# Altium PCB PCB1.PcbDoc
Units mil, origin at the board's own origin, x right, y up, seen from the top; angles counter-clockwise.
Board outline 3360 x 2065 mil, 2 copper layers (Top Layer, Bottom Layer); 16 components, 42 nets, 96 pads, 3 vias.
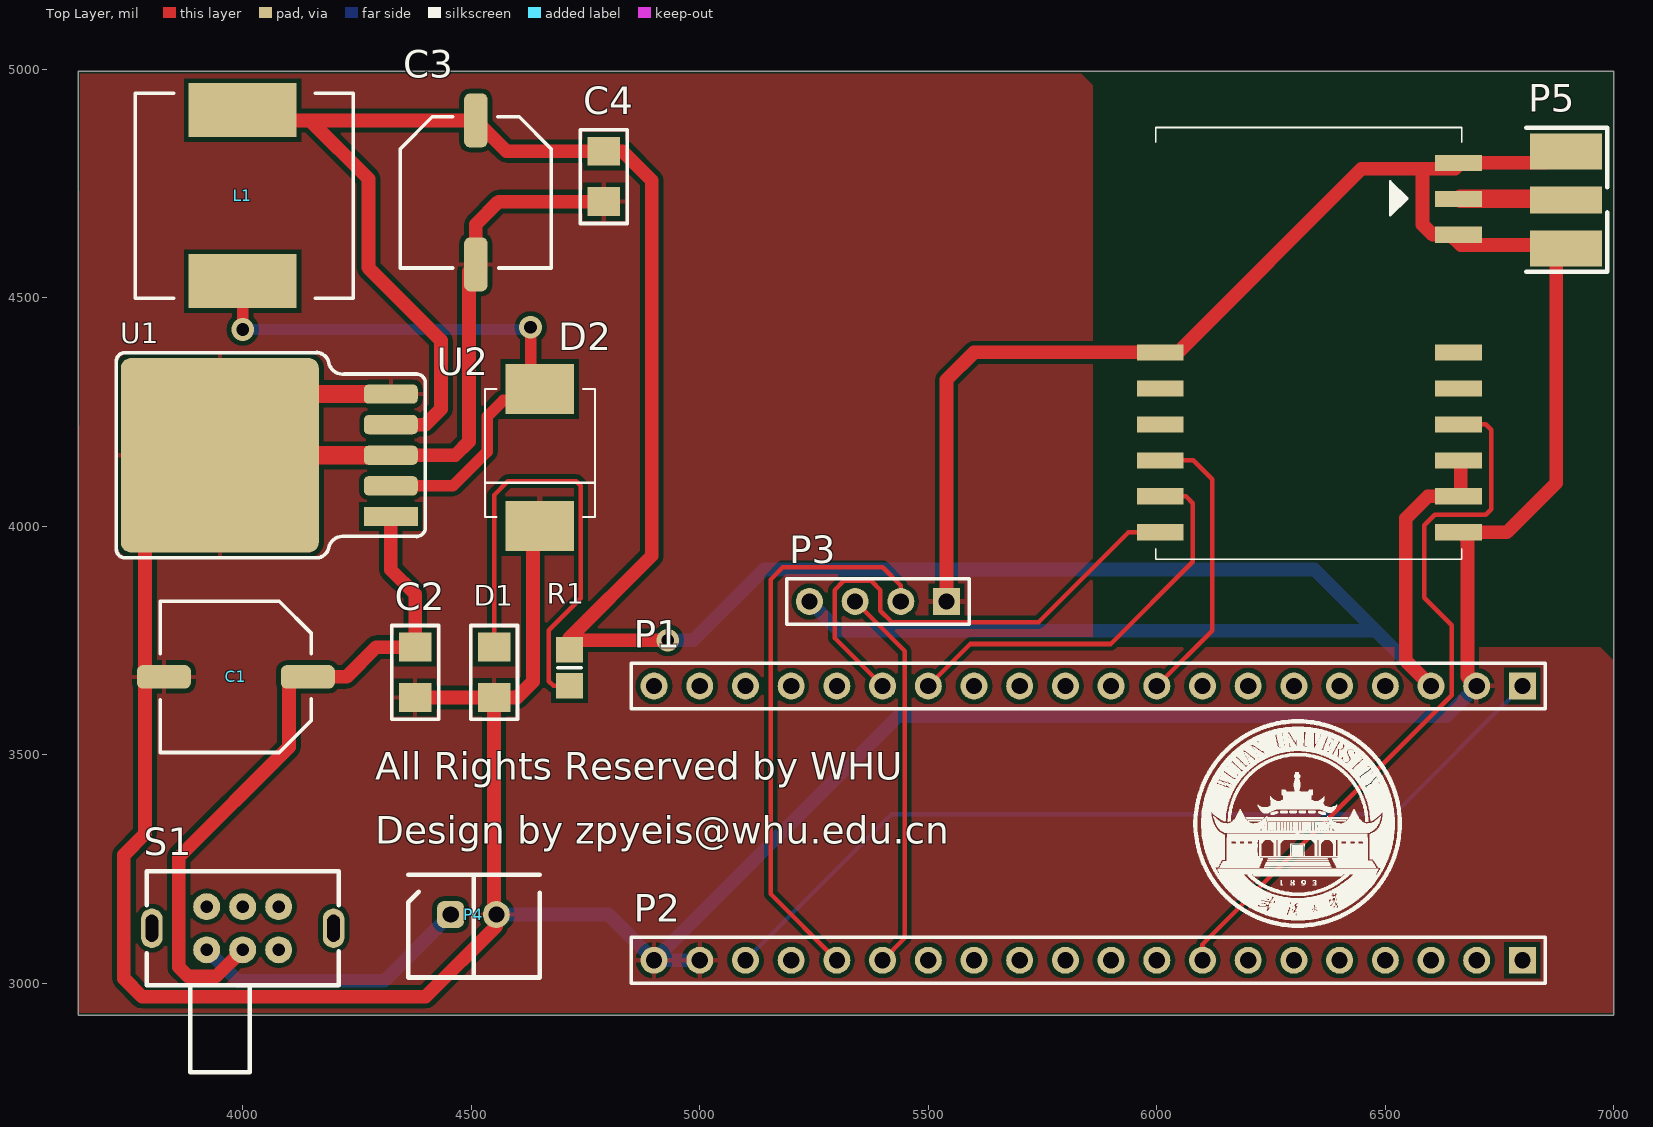
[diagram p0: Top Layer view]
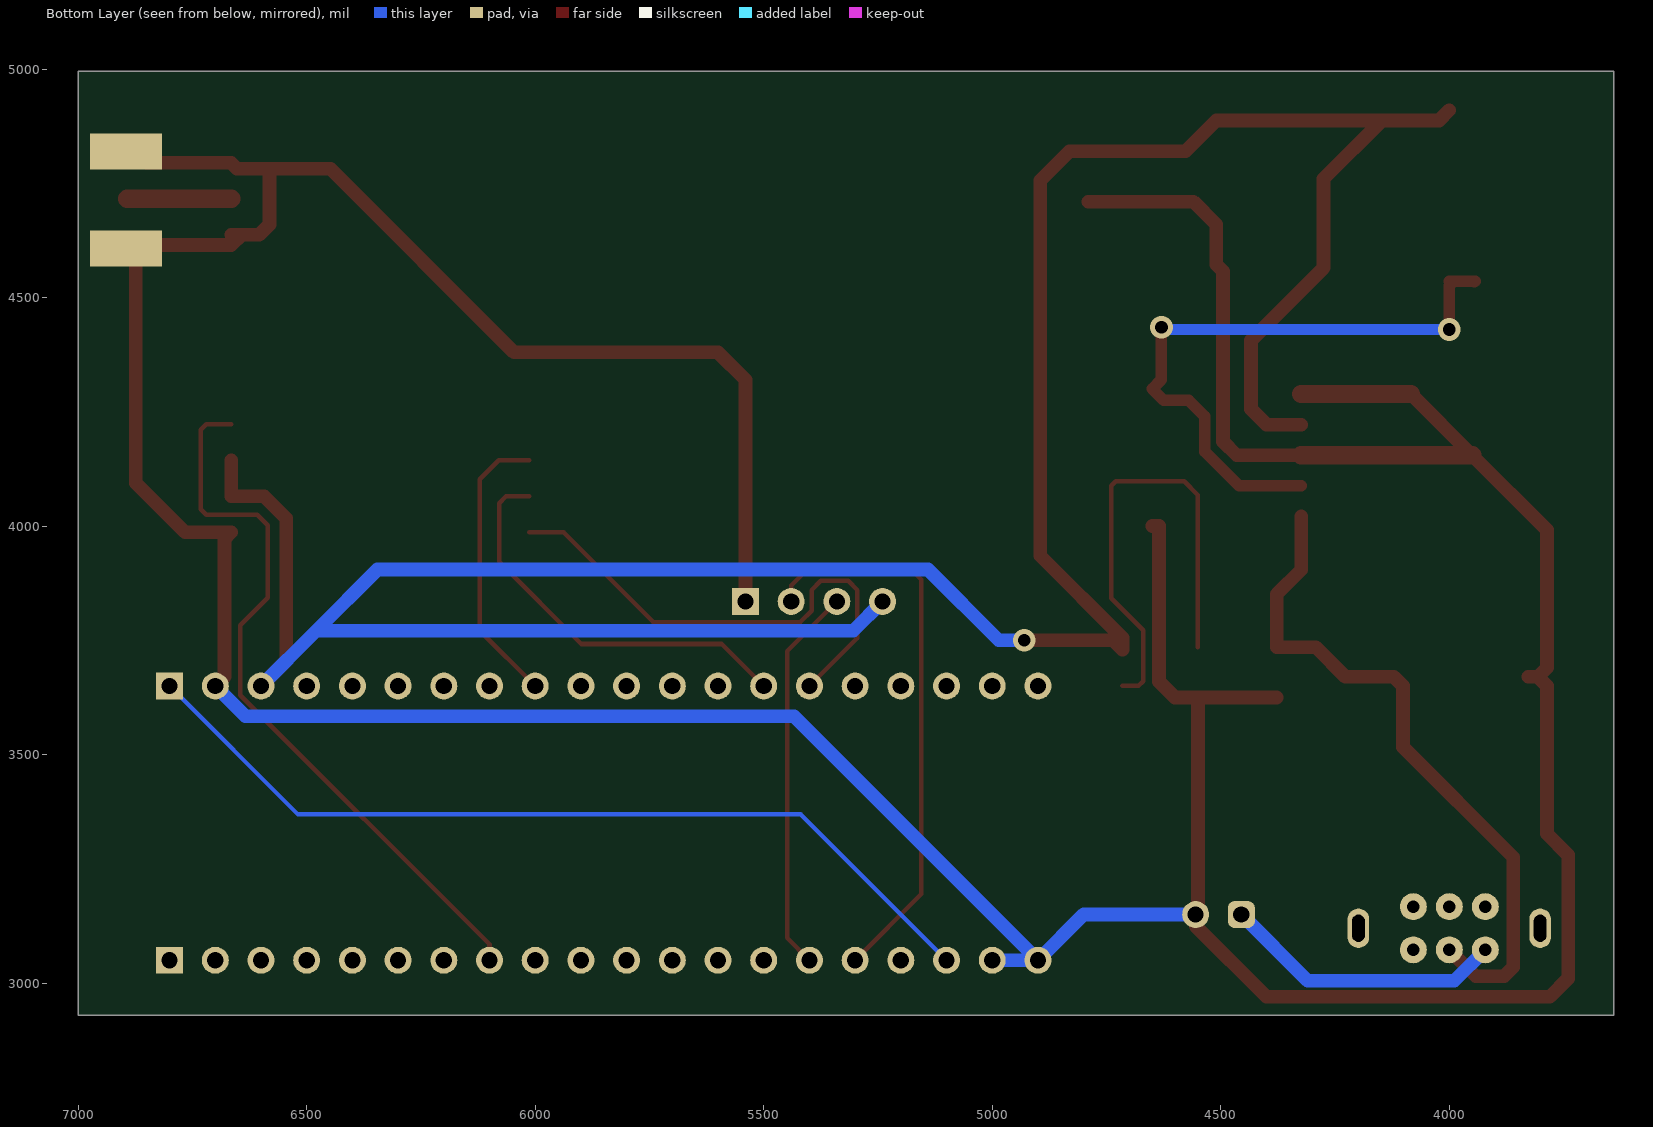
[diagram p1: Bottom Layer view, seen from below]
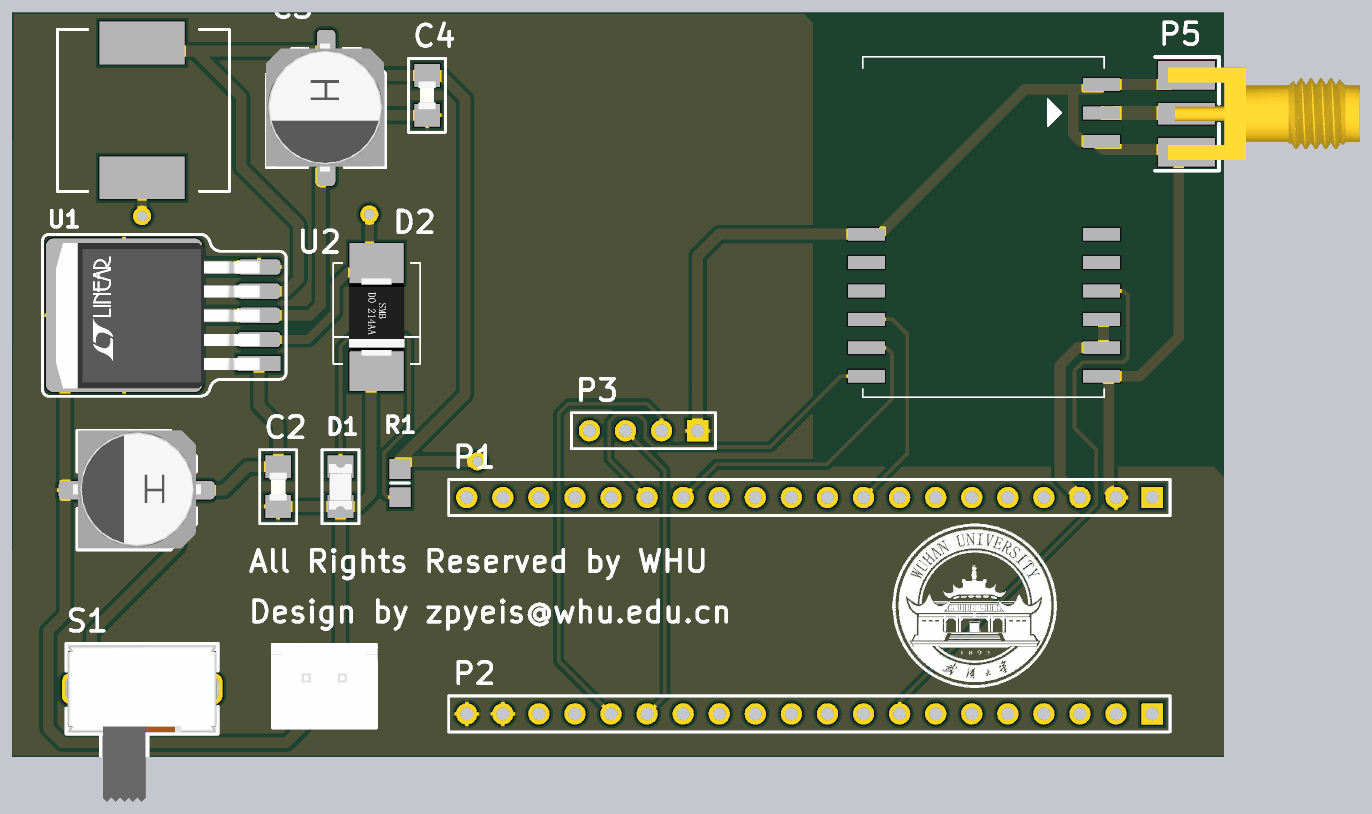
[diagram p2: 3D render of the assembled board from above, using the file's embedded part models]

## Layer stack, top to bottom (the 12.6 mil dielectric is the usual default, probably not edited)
Top Solder: solder mask 0.4, Solder Resist, Dk 3.5
Top Layer: signal copper 1.4
Dielectric 1: dielectric 12.6, FR-4, Dk 4.8
Bottom Layer: signal copper 1.4
Bottom Solder: solder mask 0.4, Solder Resist, Dk 3.5

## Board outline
3640,2930 3640,4995 7000,4995 7000,2930

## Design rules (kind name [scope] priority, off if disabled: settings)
Clearance [All] p1: gap=10 ignorepadtopadclearanceinfootprint=FALSE except(0: Arc-Hole Track-Hole SMDPad-Hole THPad-Hole Via-Hole Fill-Hole Poly-Hole Region-Hole Text-Hole; 2: Arc-Text Track-Text SMDPad-Text THPad-Text Via-Text Fill-Text Poly-Text Region-Text Text-Text)
PolygonConnect [All] p1: connectstyle=Relief reliefconductorwidth=10 reliefentries=4 polygonreliefangle="90 Angle" airgapwidth=10
RoutingVias [All] p1: holewidth=28 width=50 viastyle="Through Hole" minholewidth=28 minwidth=50 maxholewidth=28 maxwidth=50
SilkToSolderMaskClearance [IsPad] p1: minsilkscreentomaskgap=1 clearancetoexposedcopper=TRUE
SolderMaskExpansion [All] p1: expansion=4
Width [All] p1: maxlimit=40 minlimit=10 preferedwidth=10 minimp=50.000000 maximp=50.000000 favimp=50.000000
29 further rules are at their usual default settings.

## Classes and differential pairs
component class Sheet1: C1 C2 C3 C4 D1 L1 P1 P3 P4 P5 R1 S1 U1 U2

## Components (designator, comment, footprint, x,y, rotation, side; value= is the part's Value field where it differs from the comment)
C1 "CAP1" CAP+ 3985,3670 r180 top
C2 "CAP" CAP 4377.36,3680 r270 top
C3 "CAP1" CAP+ 4510,4730 r270 top
C4 "CAP" CAP 4790,4765 r270 top
D1 "LED" LED 4550,3680.12 r270 top
D2 "SS34" SS34 4650,4150 r90 top
L1 "Inductor" 470 4000,4910 r270 top value=47uH
P1 "STM32" HDR1X20 6800,3650 r180 top
P2 "STM32" HDR1X20 6800,3050 r180 top
P3 "Sensor" HDR1X4 5540,3835 r180 top
P4 "Header 2" HDR2 4455,3150 r0 top
P5 "SMB" SMA-KE 6895,4713.7 r270 top
R1 "4.7k" 6-0805_M 4715,3690 r270 top
S1 "SW-SPST" SK-22D02 4000,3120 r0 top
U1 "LM2596-5V" LM2596S 4137.01,4155 r90 top
U2 "LORA" LORA 4413.84,3842.18 r90 top

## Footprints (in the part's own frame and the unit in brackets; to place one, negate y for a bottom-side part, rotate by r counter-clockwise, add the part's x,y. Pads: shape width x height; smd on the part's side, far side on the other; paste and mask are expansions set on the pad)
6-0805_M [mm] "Chip Resistor, Body 2.0x1.2mm, IPC Low Density"
  rect 1.4x1.5 smd: 1(-1,0) 2(1,0)
  silkscreen extent 0,-0.65 0,0.65, body extent -1.07,-0.7 1.07,0.7, height 0.7
470 [mm]
  rect 3x6 smd: 1(0,0) 2(9.5,0)
  silkscreen extent -0.95,-5.97 10.45,6.15
CAP [mm]
  rect 1.6x1.8 smd: 1(-1.4,0) 2(1.4,0)
  silkscreen extent -2.6,-1.3 2.62,1.3, body extent -1,-0.62 1,0.63, height 0.5
CAP+ [mm]
  rrect50% 3x1.3 smd: 1(-4,0) 2(4,0)
  silkscreen extent -4.2,-4.2 4.2,4.2, body extent -4.52,-4.22 4.48,4.08, height 10.5
HDR1X4 [mm] "Connector; Header; 4 Position"
  rect 1.5x1.5 hole 0.9: 1(0,0)
  round 1.5 hole 0.9: 2(2.54,0) 3(5.08,0) 4(7.62,0)
  silkscreen extent -1.27,-1.27 8.89,1.27
HDR1X20 [mm] "Connector; Header; 20 Position"
  rect 1.5x1.5 hole 0.9: 1(0,0)
  round 1.5 hole 0.9: 2(2.54,0) 3(5.08,0) 4(7.62,0) 5(10.16,0) 6(12.7,0) 7(15.24,0) 8(17.78,0) 9(20.32,0) 10(22.86,0) 11(25.4,0) 12(27.94,0) 13(30.48,0) 14(33.02,0) 15(35.56,0) 16(38.1,0) 17(40.64,0) 18(43.18,0) 19(45.72,0) 20(48.26,0)
  silkscreen extent -1.27,-1.27 49.53,1.27
HDR2 [mm]
  rrect50% 1.5x1.5 hole 0.9: 1(0,0)
  round 1.5 hole 0.9: 2(2.54,0)
  silkscreen extent -2.36,-3.5 4.94,2.2, body extent -2.48,-3.55 5.02,2.45, height 7
LED [mm]
  rect 1.6x1.8 smd: 1(-1.4,0) 2(1.4,0)
  silkscreen extent -2.6,-1.3 2.62,1.3, body extent -1.57,-0.8 1.63,0.8, height 1.1
LM2596S [mm]
  rrect10% 10.8x11 smd: 0(0,4.75)
  rect 1.07x3 smd: 1(-3.4,-4.75)
  rrect50% 1.07x3 smd: 2(-1.7,-4.75) 3(0,-4.75) 4(1.7,-4.75) 5(3.4,-4.75)
  silkscreen extent -5.7,-6.66 5.7,10.5, body extent -5.14,-4.8 5.09,9.55, height 4.48
LORA [mm]
  rect 0.9x2.6 smd: 1(24.193,-57.052) 2(22.193,-57.052) 3(20.193,-57.052) 4(13.661,-57.052) 5(11.661,-57.052) 6(9.661,-57.052) 7(7.661,-57.052) 8(5.661,-57.052) 9(3.661,-57.052) 10(3.661,-40.484) 11(5.661,-40.484) 12(7.661,-40.484) 13(9.661,-40.484) 14(11.661,-40.484) 15(13.661,-40.484)
  silkscreen extent 2.16,-57.23 26.16,-40.23
SK-22D02 [mm] "10.4x6.1x4.2mm(长宽高)，脚距：2mm"
  oval 1.2x2.2 hole 0.7 slot 1.5 at 90 deg: 0(-5.05,0) 0(5.05,0)
  round 1.5 hole 0.7: 1(-2,-1.2) 2(0,-1.2) 3(2,-1.2) 4(2,1.2) 5(0,1.2) 6(-2,1.2)
  silkscreen extent -5.33,-8 5.33,3.17, body extent -5.27,-7.96 5.25,3.05, height 5.59
SMA-KE [mm] "SMA 偏脚射频天线座"
  rect 1.5x4 smd: 1(0,0)
  rect 2x4 smd: 2(-2.7,0) 2(2.7,0)
  rect 2x4 smd far side: 3(-2.7,0) 3(2.7,0)
  silkscreen extent -4,-2.2 4,2.3, body extent -3.25,-1.3 3.25,12.2, height 3.75
SS34 [mil]
  rect 110x150 smd: 1(-149.99,0.01) 2(150.01,0.01)
  silkscreen extent -130,-121 150,120, body extent -110,-77 110,77

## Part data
D2: library part DIODE
P1 P2: library part "Header 20", "Header, 20-Pin"
P3: library part "Header 4", "Header, 4-Pin"
P4: "Header, 2-Pin"
P5: "SMB Straight Connector"
R1: library part RES
S1: "Single-Pole, Single-Throw Switch"
U1: library part LM2596S
U2: library part Component_1

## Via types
v1: diameter 50, hole 28, Top Layer to Bottom Layer, 3 vias

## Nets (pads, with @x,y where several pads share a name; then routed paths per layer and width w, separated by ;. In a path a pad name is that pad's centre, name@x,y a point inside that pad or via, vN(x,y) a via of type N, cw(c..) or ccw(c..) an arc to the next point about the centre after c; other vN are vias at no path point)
5V: C3.1 C4.1 L1.1 P1.3 P3.4 R1.1 U1.4 U2.7 U2.8 | length 6871.6
  Top Layer w30: L1.1 4022.52,4887.48 4147.52,4887.48 ; U1.4 4400,4221.93 4434,4255.93 4434,4406 4275,4565 4275,4760 4147.52,4887.48 ; v1(4930,3750) 4735.63,3750 R1.1 4715,3755 4895,3935 4895,4756 4830.88,4820.12 C4.1 4577.36,4820.12 C3.1 4147.52,4887.48 ; P1.3 6545,3705 6545,4017 6593.04,4065.04 6637.32,4065.04 6665,4065.04 6665,4077.52 U2.7@6665,4143.78
  Bottom Layer w30: v1(4930,3750) 4985.63,3750 5140.63,3905 6345,3905 6479,3771 ; P3.4 5304,3771 6479,3771 ; P1.3 6479,3771
GND: C1.2 C2.2 C3.2 C4.2 D1.2 D2.1 P1.2 P2.19 P2.20 P3.1 P4.2 P5.2 U1.0 U1.3 U1.5 U2.1 U2.3 U2.9 U2.15 | length 11211.2
  Top Layer w30: C1.2 C1.2@3806.26,3670 ; U1.0@4083.86,4288.86 U1.0 3786.26,3991.26 3786.26,3690 C1.2@3806.26,3670 ; U1.3 4465,4155 4495,4185 4495,4557.52 C3.2 4510,4659.88 4560,4709.88 C4.2 ; C2.2 4463,3624.88 4463.12,3625 D1.2 ; D2.1 4635,4000.01 4635,3660 4600,3625 D1.2 ; P3.1 5540,4320 5600,4380 5985,4380 6012.68,4380 6046.15,4380 6448.11,4781.96 6587.28,4781.96 ; U2.3@6665,4637.19 U2.3@6642.81,4637.19 ; P1.2 6680,3670 6680,3971.3 6665,3986.3 6680,3986.3 6766,3986.3 6874,4094.3 P5.2@6874,4586.4 ; P5.2@6880,4825 6849.67,4794.67 6665,4794.67 6652.28,4781.96 6637.32,4781.96 6587.28,4781.96 ; P5.2@6895,4607.4 6887.4,4615 6665,4615 U2.3@6642.81,4637.19 ; C1.2@3806.26,3670 3786.26,3650 3786.26,3326.74 3740,3280.48 3740,3010 3780,2970 4400,2970 4555,3125 P4.2 4550,3155 D1.2 ; 6587.28,4781.96 6581.42,4776.09 6581.42,4660 6604.22,4637.19 U2.3@6642.81,4637.19
  Top Layer w40: U1.0 U1.3 ; U1.0@4083.86,4288.86 U1.5
  Bottom Layer w30: P4.2 4800,3150 P2.20 ; P2.19 P2.20 ; P1.2 6634,3584 5434,3584 P2.20
IN+: P4.1 S1.1 | length 621.9
  Bottom Layer w30: S1.1 3989.02,3005 4310,3005 P4.1
NetC1_1: C1.1 C2.1 S1.2 U1.1 | length 1506.6
  Top Layer w30: S1.2 3942.24,3015 3880,3015 3860,3035 3860,3275.48 4101.22,3516.7 4101.22,3650 4121.22,3670 4134,3670 C1.1 4227,3670 4292.12,3735.12 C2.1 4377.36,3851 4324.02,3904.35 U1.1
NetD1_1: D1.1 R1.2 | length 1044.8
  Top Layer w10: D1.1 4550,4068 4580,4098 4730,4098 4740,4088 4740,3842 4670,3772 4670,3660.63 4680,3650.63 R1.2
NetD2_2: D2.2 L1.2 U1.2 | length 1404.2
  Top Layer w25: L1.2@3945,4533.99 3943,4535.99 L1.2 3995,4530.99 4000,4525.99 v1(4000,4430) ; U1.2 4460.07,4088.07 4535,4163 4535,4240 4570,4275 4624.98,4275 D2.2 4630,4320 v1(4630,4435)
  Bottom Layer w25: v1(4000,4430) 4625,4430 v1(4630,4435)
NetP5_1: P5.1 U2.2 | length 230.9
  Top Layer w10: P5.1@6892.77,4715.93 P5.1
  Top Layer w40: U2.2@6665,4715.93 P5.1@6892.77,4715.93
PA0: P2.5
PA1: P2.6
PA2: P2.7
PA3: P2.8 U2.6 | length 1609.2
  Top Layer w10: P2.8 6100,3085 6645,3630 6645,3783 6585,3843 6585,4001.41 6608.59,4025 6720,4025 6732,4037 6732,4210.52 6720,4222.52 U2.6@6665,4222.52
PA4: P2.9
PA5: P2.10
PA6: P2.11
PA7: P2.12
PA8: P1.16
PA9: P1.15 U2.10 | length 1124.4
  Top Layer w10: P1.15 5295,3755 5295,3860 5315,3880 5375,3880 5395,3860 5395,3815 5420,3790 5741.7,3790 5938,3986.3 U2.10@6012.68,3986.3
PA10: P1.14 U2.11 | length 892.2
  Top Layer w10: P1.14 5592,3742 5899,3742 6079,3922 6079,4050 6063.96,4065.04 U2.11@6012.68,4065.04
PA11: P1.13
PA12: P1.12
PA15: P1.11
PB0: P2.13
PB1: P2.14
PB3: P1.10
PB4: P1.9 U2.12 | length 628.2
  Top Layer w10: P1.9 6121,3771 6121,4102.78 6080,4143.78 U2.12@6012.68,4143.78
PB5: P1.8
PB6: P1.7
PB7: P1.6
PB8: P1.5
PB9: P1.4
PB10: P2.15 P3.3 | length 850.4
  Top Layer w10: P3.3 5449,3726 5449,3099 P2.15
PB11: P2.16 P3.2 | length 1240.8
  Top Layer w10: P2.16 5155,3195 5155,3883 5182,3910 5400,3910 5440,3870 P3.2
PB12: P1.20
PB13: P1.19
PB14: P1.18
PB15: P1.17
PC13: P2.2
PC14: P2.3
PC15: P2.4
RESET: P2.17
VBAT: P2.1
VCC3V3: P1.1 P2.18 | length 1948.5
  Bottom Layer w10: P2.18 5419,3369 6519,3369 P1.1
pads on no net: P5.3 S1.0 S1.3 S1.4 S1.5 S1.6 U2.4 U2.5 U2.13 U2.14

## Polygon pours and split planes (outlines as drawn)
GND on Top Layer (solid, pour order 0): 3645,4990 5835,4990 5860,4965 5860,3735.24 6969.76,3735.24 7000,3705 7000,2935 3640,2935

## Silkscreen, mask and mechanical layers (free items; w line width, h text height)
Top Overlay:
  drawing of 5882 lines, arcs and shapes, not listed
  text "All Rights Reserved by WHU" at 4290,3445 h60
  text "Design by zpyeis@whu.edu.cn" at 4290,3305 h60
Mechanical 1:
  lines w10: 3640,2945 3640,2930 ; 3640,2930 7000,2930 7000,4995 3640,4995 3640,2930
